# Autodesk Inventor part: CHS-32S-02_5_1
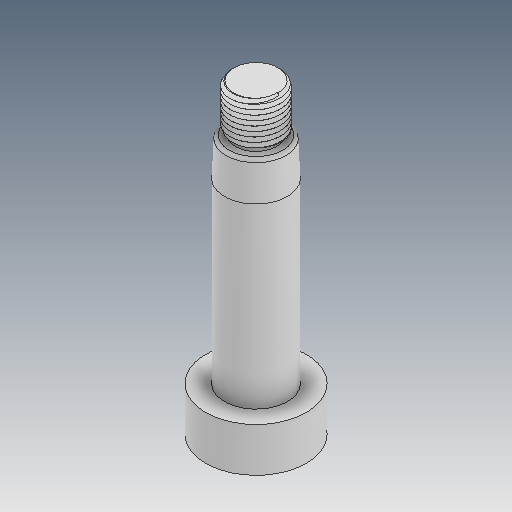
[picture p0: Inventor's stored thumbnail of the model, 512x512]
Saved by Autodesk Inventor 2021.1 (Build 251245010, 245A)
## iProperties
Created: 2021-05
Part Number: CHS-32S-02_5_1
Material: Ogólny
Document SubType Name: Modeling
Designer: user
Density: 1 g/cm^3
Appearance: Domyślna
Author: user
Revision Number: ÈÎºÎ
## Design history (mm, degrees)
feature "ÊäÈë1"
feature "ÊäÈë2"
node "Bryła1"
node "Bryła2"
